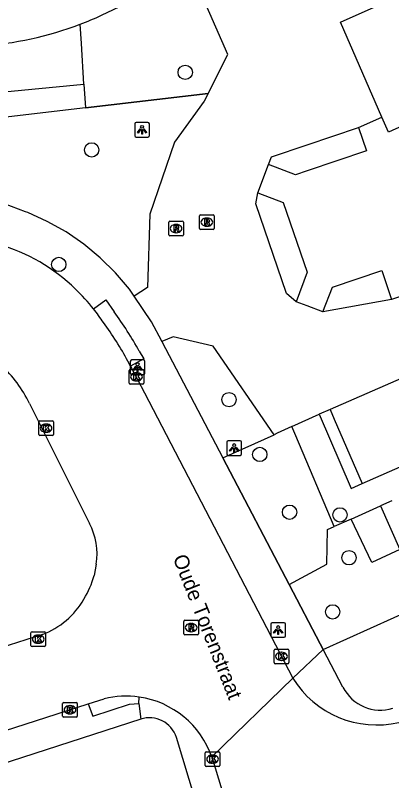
# Model space of a CAD drawing. Extents: x 161253 to 161848, y 384872 to 385383.
# Drawn here: x 161480.1 to 161505.8, y 385046.9 to 385099.1 of the extents above; entities that cross this region are included whole.
import ezdxf

# ---------------------------------------------------------------- set-up
doc = ezdxf.new("R2010")
doc.units = 0
for name, color, linetype in [('IMGEO_Boom', 7, 'Continuous'), ('IMGEO_Groenvoorziening', 7, 'Continuous'), ('IMGEO_Haag', 7, 'Continuous'), ('IMGEO_Hek', 7, 'Continuous'), ('IMGEO_Kolk', 7, 'Continuous'), ('IMGEO_Lichtpunt', 7, 'Continuous'), ('IMGEO_Muur', 7, 'Continuous'), ('IMGEO_Openbare_ruimte_label', 7, 'Continuous'), ('IMGEO_Pand', 7, 'Continuous'), ('IMGEO_Rijbaan_lokaal_open', 7, 'Continuous'), ('IMGEO_Rioolput', 7, 'Continuous'), ('IMGEO_Voetpad_gesloten', 7, 'Continuous'), ('IMGEO_Voetpad_halfverhard', 7, 'Continuous'), ('IMGEO_Voetpad_open', 7, 'Continuous')]:
    doc.layers.add(name, color=color, linetype=linetype)

msp = doc.modelspace()

# ---------------------------------------------------------------- linework, layer by layer
at = {"layer": 'IMGEO_Boom'}
for centre in [(161491.68, 385095.161), (161485.293, 385089.875), (161483.047, 385082.066), (161494.668, 385072.853), (161496.768, 385069.116), (161498.801, 385065.182), (161502.24, 385065), (161502.858, 385062.078), (161501.74, 385058.389)]:
    msp.add_circle(centre, 0.489, dxfattribs=at)
at = {"layer": 'IMGEO_Groenvoorziening'}
for points in [[(161484.766, 385094.364), (161484.591, 385097.13), (161484.502, 385098.441)], [(161476.925, 385093.612), (161484.766, 385094.364)], [(161484.766, 385094.364), (161484.879, 385092.744)], [(161484.879, 385092.744), (161493.252, 385093.724)], [(161484.879, 385092.744), (161470.726, 385091.087), (161442.697, 385087.805)], [(161505.007, 385065.612), (161506.332, 385062.63), (161504.42, 385061.76), (161502.997, 385064.717)], [(161498.766, 385060.259), (161501.355, 385061.65), (161501.392, 385064.002), (161501.846, 385064.204)], [(161501.094, 385055.82), (161512.396, 385060.909)]]:
    msp.add_lwpolyline(points, dxfattribs=at)
at = {"layer": 'IMGEO_Haag'}
for points in [[(161501.565, 385072.192), (161501.854, 385071.524), (161503.752, 385067.128)], [(161494.24, 385068.892), (161497.741, 385070.45)]]:
    msp.add_lwpolyline(points, dxfattribs=at)
at = {"layer": 'IMGEO_Hek'}
for points in [[(161493.252, 385093.724), (161484.879, 385092.744)], [(161484.879, 385092.744), (161470.726, 385091.087)]]:
    msp.add_lwpolyline(points, dxfattribs=at)
at = {"layer": 'IMGEO_Kolk'}
for p, q in [((161487.849, 385073.984), (161487.849, 385074.836)), ((161487.924, 385074.91), (161488.776, 385074.91)), ((161488.85, 385074.836), (161488.85, 385073.984)), ((161488.337, 385074.69), (161488.362, 385074.69)), ((161488.776, 385073.91), (161487.924, 385073.91)), ((161488.36, 385074.13), (161488.335, 385074.13)), ((161481.68, 385070.486), (161481.68, 385071.338)), ((161481.755, 385071.412), (161482.607, 385071.412)), ((161482.168, 385071.192), (161482.193, 385071.192)), ((161482.681, 385071.338), (161482.681, 385070.486)), ((161482.191, 385070.632), (161482.166, 385070.632)), ((161482.607, 385070.412), (161481.755, 385070.412)), ((161481.219, 385057.028), (161482.071, 385057.028)), ((161481.144, 385056.102), (161481.144, 385056.954)), ((161481.632, 385056.808), (161481.657, 385056.808)), ((161482.145, 385056.954), (161482.145, 385056.102)), ((161482.071, 385056.028), (161481.219, 385056.028)), ((161481.655, 385056.248), (161481.63, 385056.248)), ((161497.747, 385054.929), (161497.747, 385055.781)), ((161497.822, 385055.855), (161498.674, 385055.855)), ((161498.235, 385055.635), (161498.26, 385055.635)), ((161498.748, 385055.781), (161498.748, 385054.929)), ((161498.258, 385055.075), (161498.233, 385055.075)), ((161498.674, 385054.855), (161497.822, 385054.855)), ((161483.311, 385051.289), (161483.311, 385052.141)), ((161483.386, 385052.215), (161484.238, 385052.215)), ((161483.799, 385051.995), (161483.824, 385051.995)), ((161484.312, 385052.141), (161484.312, 385051.289)), ((161483.822, 385051.435), (161483.797, 385051.435)), ((161484.238, 385051.215), (161483.386, 385051.215)), ((161493.042, 385047.924), (161493.042, 385048.776)), ((161493.117, 385048.85), (161493.969, 385048.85)), ((161493.53, 385048.63), (161493.555, 385048.63)), ((161494.043, 385048.776), (161494.043, 385047.924)), ((161493.969, 385047.85), (161493.117, 385047.85)), ((161493.553, 385048.07), (161493.528, 385048.07))]:
    msp.add_line(p, q, dxfattribs=at)
for points in [[(161487.849, 385073.984), (161487.849, 385074.836)], [(161487.924, 385074.91), (161488.776, 385074.91)], [(161488.85, 385074.836), (161488.85, 385073.984)], [(161488.17, 385074.61), (161488.293, 385074.61), (161488.293, 385074.459), (161488.423, 385074.61), (161488.587, 385074.61), (161488.441, 385074.459), (161488.594, 385074.21), (161488.442, 385074.21), (161488.357, 385074.374), (161488.293, 385074.307), (161488.293, 385074.21), (161488.17, 385074.21), (161488.17, 385074.61)], [(161488.776, 385073.91), (161487.924, 385073.91)], [(161481.68, 385070.486), (161481.68, 385071.338)], [(161481.755, 385071.412), (161482.607, 385071.412)], [(161482.001, 385071.112), (161482.124, 385071.112), (161482.124, 385070.961), (161482.254, 385071.112), (161482.418, 385071.112), (161482.272, 385070.961), (161482.425, 385070.712), (161482.273, 385070.712), (161482.188, 385070.876), (161482.124, 385070.809), (161482.124, 385070.712), (161482.001, 385070.712), (161482.001, 385071.112)], [(161482.681, 385071.338), (161482.681, 385070.486)], [(161482.607, 385070.412), (161481.755, 385070.412)], [(161481.219, 385057.028), (161482.071, 385057.028)], [(161481.144, 385056.102), (161481.144, 385056.954)], [(161481.465, 385056.728), (161481.588, 385056.728), (161481.588, 385056.577), (161481.718, 385056.728), (161481.882, 385056.728), (161481.736, 385056.577), (161481.889, 385056.328), (161481.737, 385056.328), (161481.652, 385056.492), (161481.588, 385056.425), (161481.588, 385056.328), (161481.465, 385056.328), (161481.465, 385056.728)], [(161482.145, 385056.954), (161482.145, 385056.102)], [(161482.071, 385056.028), (161481.219, 385056.028)], [(161497.747, 385054.929), (161497.747, 385055.781)], [(161497.822, 385055.855), (161498.674, 385055.855)], [(161498.068, 385055.555), (161498.191, 385055.555), (161498.191, 385055.404), (161498.321, 385055.555), (161498.485, 385055.555), (161498.339, 385055.404), (161498.492, 385055.155), (161498.34, 385055.155), (161498.255, 385055.319), (161498.191, 385055.252), (161498.191, 385055.155), (161498.068, 385055.155), (161498.068, 385055.555)], [(161498.748, 385055.781), (161498.748, 385054.929)], [(161498.674, 385054.855), (161497.822, 385054.855)], [(161483.311, 385051.289), (161483.311, 385052.141)], [(161483.386, 385052.215), (161484.238, 385052.215)], [(161483.632, 385051.915), (161483.755, 385051.915), (161483.755, 385051.764), (161483.885, 385051.915), (161484.049, 385051.915), (161483.903, 385051.764), (161484.056, 385051.515), (161483.904, 385051.515), (161483.819, 385051.679), (161483.755, 385051.612), (161483.755, 385051.515), (161483.632, 385051.515), (161483.632, 385051.915)], [(161484.312, 385052.141), (161484.312, 385051.289)], [(161484.238, 385051.215), (161483.386, 385051.215)], [(161493.042, 385047.924), (161493.042, 385048.776)], [(161493.117, 385048.85), (161493.969, 385048.85)], [(161494.043, 385048.776), (161494.043, 385047.924)], [(161493.363, 385048.55), (161493.486, 385048.55), (161493.486, 385048.399), (161493.616, 385048.55), (161493.78, 385048.55), (161493.634, 385048.399), (161493.787, 385048.15), (161493.635, 385048.15), (161493.55, 385048.314), (161493.486, 385048.247), (161493.486, 385048.15), (161493.363, 385048.15), (161493.363, 385048.55)], [(161493.969, 385047.85), (161493.117, 385047.85)]]:
    msp.add_lwpolyline(points, dxfattribs=at)
for centre, start, end in [((161487.926, 385074.834), 91.552, 178.448), ((161487.926, 385074.834), 91.552, 178.448), ((161488.774, 385074.834), 1.552, 88.448), ((161488.774, 385074.834), 1.552, 88.448), ((161487.926, 385073.986), 181.552, 268.448), ((161487.926, 385073.986), 181.552, 268.448), ((161488.774, 385073.986), 271.552, 358.448), ((161488.774, 385073.986), 271.552, 358.448), ((161481.757, 385071.336), 91.552, 178.448), ((161481.757, 385071.336), 91.552, 178.448), ((161482.605, 385071.336), 1.552, 88.448), ((161482.605, 385071.336), 1.552, 88.448), ((161481.757, 385070.488), 181.552, 268.448), ((161481.757, 385070.488), 181.552, 268.448), ((161482.605, 385070.488), 271.552, 358.448), ((161482.605, 385070.488), 271.552, 358.448), ((161481.221, 385056.952), 91.552, 178.448), ((161481.221, 385056.952), 91.552, 178.448), ((161482.069, 385056.952), 1.552, 88.448), ((161482.069, 385056.952), 1.552, 88.448), ((161481.221, 385056.104), 181.552, 268.448), ((161481.221, 385056.104), 181.552, 268.448), ((161482.069, 385056.104), 271.552, 358.448), ((161482.069, 385056.104), 271.552, 358.448), ((161497.824, 385055.779), 91.552, 178.448), ((161497.824, 385055.779), 91.552, 178.448), ((161498.672, 385055.779), 1.552, 88.448), ((161498.672, 385055.779), 1.552, 88.448), ((161497.824, 385054.931), 181.552, 268.448), ((161497.824, 385054.931), 181.552, 268.448), ((161498.672, 385054.931), 271.552, 358.448), ((161498.672, 385054.931), 271.552, 358.448), ((161483.388, 385052.139), 91.552, 178.448), ((161483.388, 385052.139), 91.552, 178.448), ((161484.236, 385052.139), 1.552, 88.448), ((161484.236, 385052.139), 1.552, 88.448), ((161483.388, 385051.291), 181.552, 268.448), ((161483.388, 385051.291), 181.552, 268.448), ((161484.236, 385051.291), 271.552, 358.448), ((161484.236, 385051.291), 271.552, 358.448), ((161493.119, 385048.774), 91.552, 178.448), ((161493.119, 385048.774), 91.552, 178.448), ((161493.967, 385048.774), 1.552, 88.448), ((161493.967, 385048.774), 1.552, 88.448), ((161493.119, 385047.926), 181.552, 268.448), ((161493.119, 385047.926), 181.552, 268.448), ((161493.967, 385047.926), 271.552, 358.448), ((161493.967, 385047.926), 271.552, 358.448)]:
    msp.add_arc(centre, 0.0765, start, end, dxfattribs=at)
for centre, major_axis, ratio, start_param, end_param in [((161488.336, 385074.41), (-0.387, 0.002), 0.722429, 4.712389, 7.853982), ((161488.361, 385074.41), (-0.39, 0.002), 0.717154, 1.570796, 4.712389), ((161482.167, 385070.912), (-0.387, 0.002), 0.722429, 4.712389, 7.853982), ((161482.192, 385070.912), (-0.39, 0.002), 0.717154, 1.570796, 4.712389), ((161481.631, 385056.528), (-0.387, 0.002), 0.722429, 4.712389, 7.853982), ((161481.656, 385056.528), (-0.39, 0.002), 0.717154, 1.570796, 4.712389), ((161498.234, 385055.355), (-0.387, 0.002), 0.722429, 4.712389, 7.853982), ((161498.259, 385055.355), (-0.39, 0.002), 0.717154, 1.570796, 4.712389), ((161483.798, 385051.715), (-0.387, 0.002), 0.722429, 4.712389, 7.853982), ((161483.823, 385051.715), (-0.39, 0.002), 0.717154, 1.570796, 4.712389), ((161493.529, 385048.35), (-0.387, 0.002), 0.722429, 4.712389, 7.853982), ((161493.554, 385048.35), (-0.39, 0.002), 0.717154, 1.570796, 4.712389)]:
    msp.add_ellipse(centre, major_axis=major_axis, ratio=ratio, start_param=start_param, end_param=end_param, dxfattribs=at)
at = {"layer": 'IMGEO_Lichtpunt'}
for p, q in [((161488.233, 385091.652), (161488.233, 385090.845)), ((161488.233, 385091.652), (161488.233, 385090.845)), ((161489.135, 385091.747), (161488.327, 385091.747)), ((161489.135, 385091.747), (161488.327, 385091.747)), ((161489.229, 385090.845), (161489.229, 385091.652)), ((161489.229, 385090.845), (161489.229, 385091.652)), ((161488.327, 385090.751), (161489.135, 385090.751)), ((161488.327, 385090.751), (161489.135, 385090.751)), ((161487.928, 385075.463), (161487.928, 385074.656)), ((161487.928, 385075.463), (161487.928, 385074.656)), ((161488.83, 385075.558), (161488.022, 385075.558)), ((161488.83, 385075.558), (161488.022, 385075.558)), ((161488.924, 385074.656), (161488.924, 385075.463)), ((161488.924, 385074.656), (161488.924, 385075.463)), ((161488.022, 385074.562), (161488.83, 385074.562)), ((161488.022, 385074.562), (161488.83, 385074.562)), ((161495.423, 385070.051), (161494.615, 385070.051)), ((161495.423, 385070.051), (161494.615, 385070.051)), ((161494.521, 385069.956), (161494.521, 385069.149)), ((161494.521, 385069.956), (161494.521, 385069.149)), ((161495.517, 385069.149), (161495.517, 385069.956)), ((161495.517, 385069.149), (161495.517, 385069.956)), ((161494.615, 385069.055), (161495.423, 385069.055)), ((161494.615, 385069.055), (161495.423, 385069.055)), ((161497.52, 385057.554), (161497.52, 385056.747)), ((161497.52, 385057.554), (161497.52, 385056.747)), ((161498.422, 385057.649), (161497.614, 385057.649)), ((161498.422, 385057.649), (161497.614, 385057.649)), ((161498.516, 385056.747), (161498.516, 385057.554)), ((161498.516, 385056.747), (161498.516, 385057.554)), ((161497.614, 385056.653), (161498.422, 385056.653)), ((161497.614, 385056.653), (161498.422, 385056.653))]:
    msp.add_line(p, q, dxfattribs=at)
for points in [[(161488.607, 385091.316), (161488.646, 385091.288), (161488.458, 385091.026), (161488.42, 385091.053), (161488.607, 385091.316)], [(161488.709, 385091.268), (161488.756, 385091.268), (161488.756, 385090.946), (161488.709, 385090.946), (161488.709, 385091.268)], [(161488.819, 385091.288), (161488.857, 385091.315), (161489.044, 385091.053), (161489.005, 385091.025), (161488.819, 385091.288)], [(161488.302, 385075.127), (161488.341, 385075.099), (161488.153, 385074.837), (161488.115, 385074.864), (161488.302, 385075.127)], [(161488.404, 385075.079), (161488.451, 385075.079), (161488.451, 385074.757), (161488.404, 385074.757), (161488.404, 385075.079)], [(161488.514, 385075.099), (161488.552, 385075.126), (161488.739, 385074.864), (161488.7, 385074.836), (161488.514, 385075.099)], [(161494.895, 385069.62), (161494.934, 385069.592), (161494.746, 385069.33), (161494.708, 385069.357), (161494.895, 385069.62)], [(161494.997, 385069.572), (161495.044, 385069.572), (161495.044, 385069.25), (161494.997, 385069.25), (161494.997, 385069.572)], [(161495.107, 385069.592), (161495.145, 385069.619), (161495.332, 385069.357), (161495.293, 385069.329), (161495.107, 385069.592)], [(161497.894, 385057.218), (161497.933, 385057.19), (161497.745, 385056.928), (161497.707, 385056.955), (161497.894, 385057.218)], [(161497.996, 385057.17), (161498.043, 385057.17), (161498.043, 385056.848), (161497.996, 385056.848), (161497.996, 385057.17)], [(161498.106, 385057.19), (161498.144, 385057.217), (161498.331, 385056.955), (161498.292, 385056.927), (161498.106, 385057.19)]]:
    msp.add_lwpolyline(points, dxfattribs=at)
for centre in [(161488.732, 385091.45), (161488.427, 385075.261), (161495.02, 385069.754), (161498.019, 385057.352)]:
    msp.add_circle(centre, 0.0994, dxfattribs=at)
for centre, start, end in [((161488.327, 385091.652), 90, 180), ((161488.327, 385091.652), 90, 180), ((161489.135, 385091.652), 0, 90), ((161489.135, 385091.652), 0, 90), ((161488.327, 385090.845), 180, 270), ((161488.327, 385090.845), 180, 270), ((161489.135, 385090.845), 270, 0), ((161489.135, 385090.845), 270, 360), ((161488.022, 385075.463), 90, 180), ((161488.022, 385075.463), 90, 180), ((161488.83, 385075.463), 0, 90), ((161488.83, 385075.463), 0, 90), ((161488.022, 385074.656), 180, 270), ((161488.022, 385074.656), 180, 270), ((161488.83, 385074.656), 270, 0), ((161488.83, 385074.656), 270, 360), ((161494.615, 385069.956), 90, 180), ((161494.615, 385069.956), 90, 180), ((161495.423, 385069.956), 0, 90), ((161495.423, 385069.956), 0, 90), ((161494.615, 385069.149), 180, 270), ((161494.615, 385069.149), 180, 270), ((161495.423, 385069.149), 270, 0), ((161495.423, 385069.149), 270, 360), ((161497.614, 385057.554), 90, 180), ((161497.614, 385057.554), 90, 180), ((161498.422, 385057.554), 0, 90), ((161498.422, 385057.554), 0, 90), ((161497.614, 385056.747), 180, 270), ((161497.614, 385056.747), 180, 270), ((161498.422, 385056.747), 270, 0), ((161498.422, 385056.747), 270, 360)]:
    msp.add_arc(centre, 0.0946, start, end, dxfattribs=at)
at = {"layer": 'IMGEO_Muur'}
for points in [[(161490.076, 385076.838), (161490.088, 385076.816), (161494.24, 385068.892)], [(161494.24, 385068.892), (161498.766, 385060.259)], [(161498.766, 385060.259), (161500.895, 385056.199)], [(161500.895, 385056.199), (161501.094, 385055.82)]]:
    msp.add_lwpolyline(points, dxfattribs=at)
at = {"layer": 'IMGEO_Pand'}
for points in [[(161506.442, 385098.697), (161507.939, 385095.366), (161507.216, 385095.041), (161508.413, 385092.378), (161505.548, 385091.091), (161505.089, 385092.114)], [(161503.513, 385091.407), (161505.089, 385092.114)], [(161503.513, 385091.407), (161504.049, 385089.82), (161500, 385088.452), (161499.2, 385088.182), (161497.366, 385088.879)], [(161496.632, 385086.948), (161497.366, 385088.879)], [(161496.632, 385086.948), (161498.358, 385086.292), (161500.011, 385081.547), (161499.243, 385079.526)], [(161501.075, 385078.83), (161501.721, 385080.529), (161505.107, 385081.646), (161505.758, 385079.671)], [(161508.662, 385080.628), (161505.758, 385079.671)], [(161501.075, 385078.83), (161500, 385079.238), (161499.243, 385079.526)]]:
    msp.add_lwpolyline(points, dxfattribs=at)
at = {"layer": 'IMGEO_Rijbaan_lokaal_open'}
for points in [[(161487.941, 385075.14), (161487.769, 385075.465)], [(161487.941, 385075.14), (161488.906, 385073.312), (161499.021, 385053.875)], [(161481.048, 385072.601), (161485.139, 385064.411)], [(161485.605, 385061.645), (161485.461, 385060.866)], [(161481.926, 385056.849), (161477.371, 385055.388)], [(161499.021, 385053.875), (161493.5, 385048.497)], [(161485.057, 385052.122), (161486.137, 385052.468)], [(161438.593, 385037.157), (161442.724, 385038.493), (161449.422, 385040.654), (161485.057, 385052.122)], [(161493.5, 385048.497), (161500, 385027.05), (161500.236, 385026.271)]]:
    msp.add_lwpolyline(points, dxfattribs=at)
for centre, radius, start, end in [((161475.39, 385071.259), 12.683, 46.0718, 73.8168), ((161474.942, 385070.755), 13.356, 38.2988, 46.1856), ((161474.898, 385070.724), 13.411, 33.4202, 38.2869), ((161468.668, 385065.202), 21.683, 28.2492, 36.5333), ((161472.802, 385068.524), 9.198, 26.3084, 46.6041), ((161481.241, 385062.332), 4.418, 351.0536, 28.0725), ((161479.421, 385062.57), 6.276, 328.1856, 344.2412), ((161480.069, 385061.889), 5.372, 290.2271, 330.718), ((161504.733, 385057.383), 6.704, 211.5543, 283.2161), ((161487.628, 385046.425), 6.224, 81.6375, 103.8583), ((161487.628, 385046.421), 6.228, 19.4719, 81.6447)]:
    msp.add_arc(centre, radius, start, end, dxfattribs=at)
at = {"layer": 'IMGEO_Rioolput'}
for p, q in [((161492.65, 385084.528), (161492.65, 385085.38)), ((161492.725, 385085.454), (161493.577, 385085.454)), ((161493.138, 385085.234), (161493.163, 385085.234)), ((161493.651, 385085.38), (161493.651, 385084.528)), ((161490.552, 385084.087), (161490.552, 385084.939)), ((161490.627, 385085.013), (161491.479, 385085.013)), ((161491.04, 385084.793), (161491.065, 385084.793)), ((161491.553, 385084.939), (161491.553, 385084.087)), ((161493.161, 385084.674), (161493.136, 385084.674)), ((161491.063, 385084.233), (161491.038, 385084.233)), ((161493.577, 385084.454), (161492.725, 385084.454)), ((161491.479, 385084.013), (161490.627, 385084.013)), ((161491.583, 385056.89), (161491.583, 385057.742)), ((161491.658, 385057.816), (161492.51, 385057.816)), ((161492.071, 385057.596), (161492.096, 385057.596)), ((161492.584, 385057.742), (161492.584, 385056.89)), ((161492.094, 385057.036), (161492.069, 385057.036)), ((161492.51, 385056.816), (161491.658, 385056.816))]:
    msp.add_line(p, q, dxfattribs=at)
for points in [[(161492.65, 385084.528), (161492.65, 385085.38)], [(161492.725, 385085.454), (161493.577, 385085.454)], [(161493.239, 385085.152), (161492.987, 385085.154), (161492.987, 385084.754)], [(161493.651, 385085.38), (161493.651, 385084.528)], [(161490.552, 385084.087), (161490.552, 385084.939)], [(161490.627, 385085.013), (161491.479, 385085.013)], [(161491.141, 385084.711), (161490.889, 385084.713), (161490.889, 385084.313)], [(161491.067, 385084.632), (161491.013, 385084.632), (161491.013, 385084.551)], [(161491.553, 385084.939), (161491.553, 385084.087)], [(161492.987, 385084.754), (161493.111, 385084.754), (161493.111, 385084.916), (161493.122, 385084.916)], [(161493.165, 385085.073), (161493.111, 385085.073), (161493.111, 385084.992)], [(161493.111, 385084.992), (161493.163, 385084.992)], [(161493.169, 385084.887), (161493.24, 385084.754), (161493.38, 385084.754), (161493.315, 385084.88)], [(161490.889, 385084.313), (161491.013, 385084.313), (161491.013, 385084.475), (161491.024, 385084.475)], [(161491.013, 385084.551), (161491.065, 385084.551)], [(161491.071, 385084.446), (161491.142, 385084.313), (161491.282, 385084.313), (161491.217, 385084.439)], [(161493.577, 385084.454), (161492.725, 385084.454)], [(161491.479, 385084.013), (161490.627, 385084.013)], [(161491.583, 385056.89), (161491.583, 385057.742)], [(161491.658, 385057.816), (161492.51, 385057.816)], [(161492.172, 385057.514), (161491.92, 385057.516), (161491.92, 385057.116)], [(161492.584, 385057.742), (161492.584, 385056.89)], [(161491.92, 385057.116), (161492.044, 385057.116), (161492.044, 385057.278), (161492.055, 385057.278)], [(161492.098, 385057.435), (161492.044, 385057.435), (161492.044, 385057.354)], [(161492.044, 385057.354), (161492.096, 385057.354)], [(161492.102, 385057.249), (161492.173, 385057.116), (161492.313, 385057.116), (161492.248, 385057.242)], [(161492.51, 385056.816), (161491.658, 385056.816)]]:
    msp.add_lwpolyline(points, dxfattribs=at)
for centre, radius, start, end in [((161492.727, 385085.378), 0.0765, 91.552, 178.448), ((161492.727, 385085.378), 0.0765, 91.552, 178.448), ((161493.238, 385085.042), 0.109, 350.3612, 89.416), ((161493.575, 385085.378), 0.0765, 1.552, 88.448), ((161493.575, 385085.378), 0.0765, 1.552, 88.448), ((161490.629, 385084.937), 0.0765, 91.552, 178.448), ((161490.629, 385084.937), 0.0765, 91.552, 178.448), ((161491.073, 385084.536), 0.0964, 77.0061, 93.1865), ((161491.087, 385084.593), 0.0378, 276.6634, 79.6772), ((161491.14, 385084.601), 0.109, 350.3612, 89.416), ((161491.477, 385084.937), 0.0765, 1.552, 88.448), ((161491.477, 385084.937), 0.0765, 1.552, 88.448), ((161493.121, 385084.863), 0.0533, 26.0293, 88.6989), ((161493.147, 385085.181), 0.19, 274.7715, 282.9687), ((161493.171, 385084.977), 0.0964, 77.0061, 93.1865), ((161493.185, 385085.034), 0.0378, 276.6634, 79.6772), ((161493.236, 385085.042), 0.112, 277.5842, 350.9817), ((161493.22, 385084.827), 0.108, 29.5134, 73.7905), ((161490.629, 385084.089), 0.0765, 181.552, 268.448), ((161490.629, 385084.089), 0.0765, 181.552, 268.448), ((161491.023, 385084.422), 0.0533, 26.0293, 88.6989), ((161491.049, 385084.74), 0.19, 274.7715, 282.9687), ((161491.138, 385084.601), 0.112, 277.5842, 350.9817), ((161491.122, 385084.386), 0.108, 29.5134, 73.7905), ((161491.477, 385084.089), 0.0765, 271.552, 358.448), ((161491.477, 385084.089), 0.0765, 271.552, 358.448), ((161492.727, 385084.53), 0.0765, 181.552, 268.448), ((161492.727, 385084.53), 0.0765, 181.552, 268.448), ((161493.575, 385084.53), 0.0765, 271.552, 358.448), ((161493.575, 385084.53), 0.0765, 271.552, 358.448), ((161491.66, 385057.74), 0.0765, 91.552, 178.448), ((161491.66, 385057.74), 0.0765, 91.552, 178.448), ((161492.171, 385057.404), 0.109, 350.3612, 89.416), ((161492.508, 385057.74), 0.0765, 1.552, 88.448), ((161492.508, 385057.74), 0.0765, 1.552, 88.448), ((161492.054, 385057.225), 0.0533, 26.0293, 88.6989), ((161492.08, 385057.543), 0.19, 274.7715, 282.9687), ((161492.104, 385057.339), 0.0964, 77.0061, 93.1865), ((161492.118, 385057.396), 0.0378, 276.6634, 79.6772), ((161492.169, 385057.404), 0.112, 277.5842, 350.9817), ((161492.153, 385057.189), 0.108, 29.5134, 73.7905), ((161491.66, 385056.892), 0.0765, 181.552, 268.448), ((161491.66, 385056.892), 0.0765, 181.552, 268.448), ((161492.508, 385056.892), 0.0765, 271.552, 358.448), ((161492.508, 385056.892), 0.0765, 271.552, 358.448)]:
    msp.add_arc(centre, radius, start, end, dxfattribs=at)
for centre, major_axis, ratio, start_param, end_param in [((161493.137, 385084.954), (-0.387, 0.002), 0.722429, 4.712389, 7.853982), ((161493.162, 385084.954), (-0.39, 0.002), 0.717154, 1.570796, 4.712389), ((161491.039, 385084.513), (-0.387, 0.002), 0.722429, 4.712389, 7.853982), ((161491.064, 385084.513), (-0.39, 0.002), 0.717154, 1.570796, 4.712389), ((161492.07, 385057.316), (-0.387, 0.002), 0.722429, 4.712389, 7.853982), ((161492.095, 385057.316), (-0.39, 0.002), 0.717154, 1.570796, 4.712389)]:
    msp.add_ellipse(centre, major_axis=major_axis, ratio=ratio, start_param=start_param, end_param=end_param, dxfattribs=at)
at = {"layer": 'IMGEO_Voetpad_gesloten'}
msp.add_lwpolyline([(161485.958, 385099.05), (161492.12, 385101.996)], dxfattribs=at)
for centre, radius, start, end in [((161475.651, 385121.648), 24.838, 290.8774, 294.5187), ((161476.144, 385120.506), 23.595, 273.7639, 290.7461)]:
    msp.add_arc(centre, radius, start, end, dxfattribs=at)
at = {"layer": 'IMGEO_Voetpad_halfverhard'}
for points in [[(161500.827, 385071.871), (161503.003, 385066.792), (161503.752, 385067.128)], [(161501.846, 385064.204), (161499.218, 385070.39), (161498.962, 385071.03)], [(161503.752, 385067.128), (161509.142, 385069.503)], [(161505.787, 385065.959), (161505.007, 385065.612)], [(161502.997, 385064.717), (161505.007, 385065.612)], [(161502.997, 385064.717), (161501.846, 385064.204)]]:
    msp.add_lwpolyline(points, dxfattribs=at)
at = {"layer": 'IMGEO_Voetpad_open'}
for points in [[(161493.252, 385093.724), (161494.592, 385096.371), (161492.12, 385101.996)], [(161505.089, 385092.114), (161502.279, 385098.581), (161505.803, 385100.164)], [(161493.252, 385093.724), (161492.981, 385093.19), (161490.954, 385090.414), (161489.252, 385085.498), (161489.107, 385080.503), (161488.184, 385079.907)], [(161497.366, 385088.879), (161497.562, 385089.397), (161500, 385090.22), (161503.513, 385091.407)], [(161499.243, 385079.526), (161498.597, 385080.086), (161496.491, 385086.198), (161496.632, 385086.948)], [(161488.184, 385079.907), (161487.868, 385080.375), (161486.922, 385081.494), (161485.879, 385082.523), (161484.749, 385083.456), (161483.54, 385084.283), (161482.262, 385085), (161480.924, 385085.599), (161480.771, 385085.659), (161479.331, 385086.193)], [(161485.424, 385079.033), (161486.25, 385079.645), (161486.819, 385078.835)], [(161490.088, 385076.816), (161490.076, 385076.838), (161489.373, 385078.147), (161488.184, 385079.907)], [(161505.758, 385079.671), (161501.075, 385078.83)], [(161497.741, 385070.45), (161493.584, 385076.498), (161490.851, 385077.134), (161490.088, 385076.816)], [(161490.088, 385076.816), (161494.24, 385068.892)], [(161488.539, 385076.16), (161488.847, 385075.634), (161487.941, 385075.14)], [(161506.948, 385074.531), (161501.565, 385072.192)], [(161501.565, 385072.192), (161500.827, 385071.871)], [(161498.962, 385071.03), (161500.827, 385071.871)], [(161498.962, 385071.03), (161497.959, 385070.568), (161497.741, 385070.45)], [(161498.766, 385060.259), (161494.24, 385068.892)], [(161501.094, 385055.82), (161500.895, 385056.199), (161498.766, 385060.259)], [(161501.094, 385055.82), (161499.021, 385053.875)], [(161502.444, 385053.246), (161501.094, 385055.82)], [(161488.519, 385052.142), (161488.533, 385052.583)], [(161485.057, 385052.122), (161485.37, 385051.28), (161487.872, 385052.098), (161488.519, 385052.142)], [(161488.519, 385052.142), (161488.637, 385051.077)], [(161488.637, 385051.077), (161425.757, 385030.732), (161423.476, 385029.994)], [(161492.885, 385023.978), (161498.371, 385025.726), (161491.075, 385049.831)]]:
    msp.add_lwpolyline(points, dxfattribs=at)
for centre, radius, start, end in [((161468.066, 385064.887), 23.372, 28.8394, 36.6419), ((161505.014, 385054.592), 2.901, 207.6488, 286.6553), ((161489.232, 385049.232), 1.938, 17.9903, 107.8688)]:
    msp.add_arc(centre, radius, start, end, dxfattribs=at)

# ---------------------------------------------------------------- texts
at = {"layer": 'IMGEO_Openbare_ruimte_label'}
msp.add_text('Oude Torenstraat', height=1, rotation=291.5887, dxfattribs=at).set_placement((161490.817, 385062.071))

doc.saveas('drawing.dxf')
